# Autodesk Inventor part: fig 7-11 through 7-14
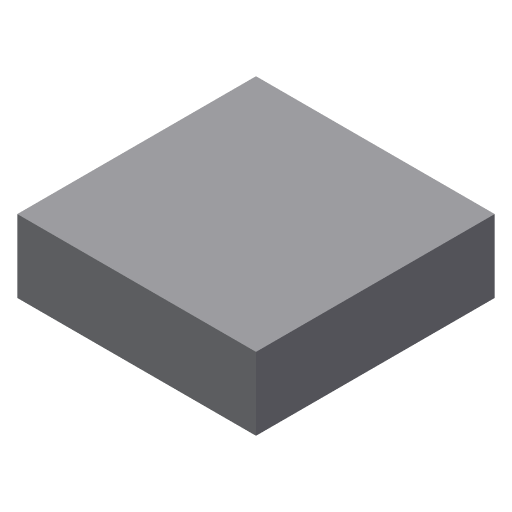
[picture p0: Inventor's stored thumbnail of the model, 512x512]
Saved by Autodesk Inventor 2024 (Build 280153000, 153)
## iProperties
Created: 2009-09
Part Number: fig 7-11 through 7-14
Document SubType Name: Modeling
Designer: Sham
Density: 1 g/cm^3
Material: Generic
Appearance: Default
Author: Sham
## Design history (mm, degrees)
sketch "Sketch1"
  geometry: L1 (-23, 20)-(0, 20); L2 (0, 20)-(0, -3); L3 (0, -3)-(-23, -3); L4 (-23, -3)-(-23, 20)
  constraints: 8 end point, 2 parallel, 1 horizontal, 1 perpendicular
  dimensions: "d2" = 23 distance of L1.start L1.end; "d3" = 23 distance of L3.end L1.start
extrude "Extrusion1" new body sketch "Sketch1" distance "d0" = 7; taper "d1" = 0 deg
body "Solid1"
